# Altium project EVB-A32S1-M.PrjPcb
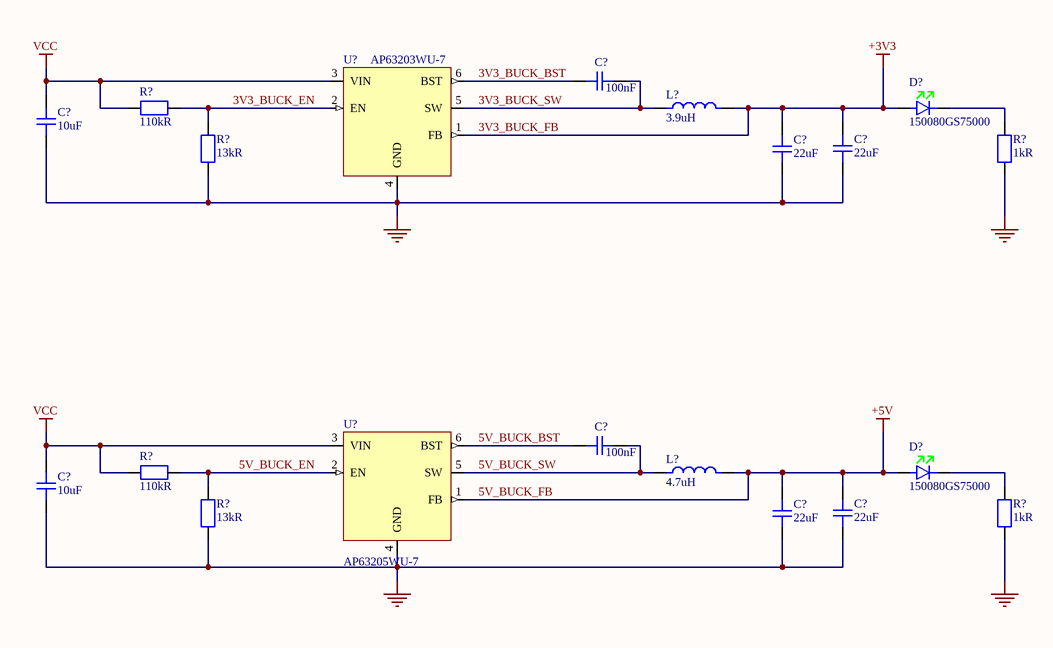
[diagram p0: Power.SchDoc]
CompanyName: Dennis Micro Computers; DrawnBy: Dennis C. M.; Title: EVB-A32S1-M
1 sheet, 20 parts. Net scope: global (net labels, ports and power ports of the same name join across sheets).

## Sheet Power.SchDoc: EVB-A32S1-M
size A4; SheetNumber: 1; SheetTotal: 1

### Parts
(Parts that share a designator on the sheet are numbered #1, #2 ... from top to bottom, then left to right.)
C?#1  value 100nF  [CAP_0402_A]  (hidden comment: CC0402MRX5R6BB104)
C?#2  value 10uF  [CAP_0805_A]  (hidden comment: CC0805KRX5R7BB106)
C?#3  value 22uF  [CAP_0805_A]  (hidden comment: CC0805MKX5R6BB226)
C?#4  value 22uF  [CAP_0805_A]  (hidden comment: CC0805MKX5R6BB226)
C?#5  value 100nF  [CAP_0402_A]  (hidden comment: CC0402MRX5R6BB104)
C?#6  value 10uF  [CAP_0805_A]  (hidden comment: CC0805KRX5R7BB106)
C?#7  value 22uF  [CAP_0805_A]  (hidden comment: CC0805MKX5R6BB226)
C?#8  value 22uF  [CAP_0805_A]  (hidden comment: CC0805MKX5R6BB226)
D?#1  150080GS75000  [150080GS75000]
D?#2  150080GS75000  [150080GS75000]
L?#1  value 3.9uH  [1255AY-XXXX=P3-Footprint-1]  (hidden comment: 1255AY-3R9N=P3)
L?#2  value 4.7uH  [1255AY-XXXX=P3-Footprint-1]  (hidden comment: 1255AY-4R7M=P3)
R?#1  value 110kR  [RES_0402_A]  (hidden comment: RC0402FR-07110KL)
R?#2  value 13kR  [RES_0402_A]  (hidden comment: RC0402FR-0713KL)
R?#3  value 1kR  [RES_0402_A]  (hidden comment: RC0402FR-071KL)
R?#4  value 110kR  [RES_0402_A]  (hidden comment: RC0402FR-07110KL)
R?#5  value 13kR  [RES_0402_A]  (hidden comment: RC0402FR-0713KL)
R?#6  value 1kR  [RES_0402_A]  (hidden comment: RC0402FR-071KL)
U?#1  AP63203WU-7  [TSOT-23-6]
U?#2  AP63205WU-7  [TSOT-23-6]

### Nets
3V3_BUCK_FB: C?#3.2 C?#4.2 D?#1.1 L?#1.2 U?#1.1(FB)  [also labelled +3V3]
5V_BUCK_FB: C?#7.2 C?#8.2 D?#2.1 L?#2.2 U?#2.1(FB)  [also labelled +5V]
GND: C?#2.1 C?#3.1 C?#4.1 C?#6.1 C?#7.1 C?#8.1 R?#2.1 R?#3.1 R?#5.1 R?#6.1 U?#1.4(GND) U?#2.4(GND)
VCC: C?#2.2 C?#6.2 R?#1.2 R?#4.2 U?#1.3(VIN) U?#2.3(VIN)
3V3_BUCK_BST: C?#1.2 U?#1.6(BST)
3V3_BUCK_EN: R?#1.1 R?#2.2 U?#1.2(EN)
3V3_BUCK_SW: C?#1.1 L?#1.1 U?#1.5(SW)
5V_BUCK_BST: C?#5.2 U?#2.6(BST)
5V_BUCK_EN: R?#4.1 R?#5.2 U?#2.2(EN)
5V_BUCK_SW: C?#5.1 L?#2.1 U?#2.5(SW)
NetD?#1_2: D?#1.2 R?#3.2
NetD?#2_2: D?#2.2 R?#6.2

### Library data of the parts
C?#1 C?#5 = CMP-001-00009-5: Multilayer Ceramic Capacitor, 0.1 uF, 25 V, ± 20%, X7R, 0402 [1005 Metric]; Dielectric: X5R; Temperature Coefficient: 30ppm/°C; Voltage Rating: 10V
C?#2 C?#6 = CMP-001-00018-1: 0805 10 uF 16 V ±10% Tolerance X5R Multilayer Ceramic Chip Capacitor; Voltage Rating (DC): 16V
C?#3 C?#4 C?#7 C?#8 = CMP-001-00014-3: Multilayer Ceramic Capacitor, 22 uF, 10 V, ± 20%, X5R, 0805 [2012 Metric]; Voltage Rating (DC): 10V
D?#1 D?#2 = CMP-007-00000-3: WURTH ELEKTRONIK - 150080GS75000 - LED, Green, SMD, 0805, 30 mA, 3.2 V, 520 nm; Forward Current: 30mA; Forward Voltage: 3.2V; Luminous Intensity: 450mcd; Max Reverse Voltage (DC): 5V; Lens Transparency: Clear; Power Dissipation: 105mW; Lens Style: Clear,Flat,Rectangular; Lens Size: 1.25mm; Viewing Angle: 140°; Test Current: 20mA; Dominant Wavelength: 520nm; Lens Color: Colorless
L?#1 = CMP-006-00002-1: Inductor Power Shielded Wirewound 3.9uH 30% 100KHz Ferrite 4.2A 0.0264Ohm DCR 2424 T/R; DC Resistance (DCR): 26.4mR; Saturation Current: 4.7A
L?#2 = CMP-006-00001-4: Inductor Power Shielded Wirewound 4.7uH 20% 100KHz Ferrite 4A 0.0276Ohm DCR 2424 T/R; DC Resistance (DCR): 27.6mR; Current Rating: 4.5A
R?#1 R?#4 = CMP-009-00000-5: SMD Chip Resistor, 110 kOhm, ± 1%, 63 mW, 0402 [1005 Metric], Thick Film, General Purpose; Max Power Dissipation: 63mW; Voltage Rating (DC): 50V; Temperature Coefficient: 100ppm/°C
R?#2 R?#5 = CMP-009-00001-5: SMD Chip Resistor, 13 kOhm, ± 1%, 63 mW, 0402 [1005 Metric], Thick Film, General Purpose; Temperature Coefficient: 100ppm/°C; Voltage Rating: 50V; Max Power Dissipation: 63mW; Power Rating: 62.5mW
R?#3 R?#6 = CMP-009-00002-5: SMD Chip Resistor, 1 kOhm, ± 1%, 62.5 mW, 0402 [1005 Metric], Thick Film, General Purpose; Temperature Coefficient: 100ppm/°C; Voltage Rating (AC): 50V; Power Rating: 62.5mW; Max Power Dissipation: 63mW
U?#1 = CMP-019-00004-4: AP63203 Series 3.3 V 2 A SMT Fixed Low IQ Synchronous Buck - TSOT-26; Max Duty Cycle: 100%; Output Voltage: 3.3V; Number of Outputs: 1; Max Supply Voltage: 32V; Switching Frequency: 1.1MHz; Min Supply Voltage: 3.8V; Nominal Supply Current: 22uA; Output Current: 2A
U?#2 = CMP-019-00003-4: AP63205 Series 32 V 2 A 1.1 MHz Synchronous Buck Converter -TSOT-26; Number of Outputs: 1; Max Duty Cycle: 100%; Output Current: 2A; Switching Frequency: 1.1MHz; Max Supply Voltage: 32V; Output Voltage: 5V; Nominal Supply Current: 22uA; Min Supply Voltage: 3.8V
